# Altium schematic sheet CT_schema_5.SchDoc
size 176 x 147 mm
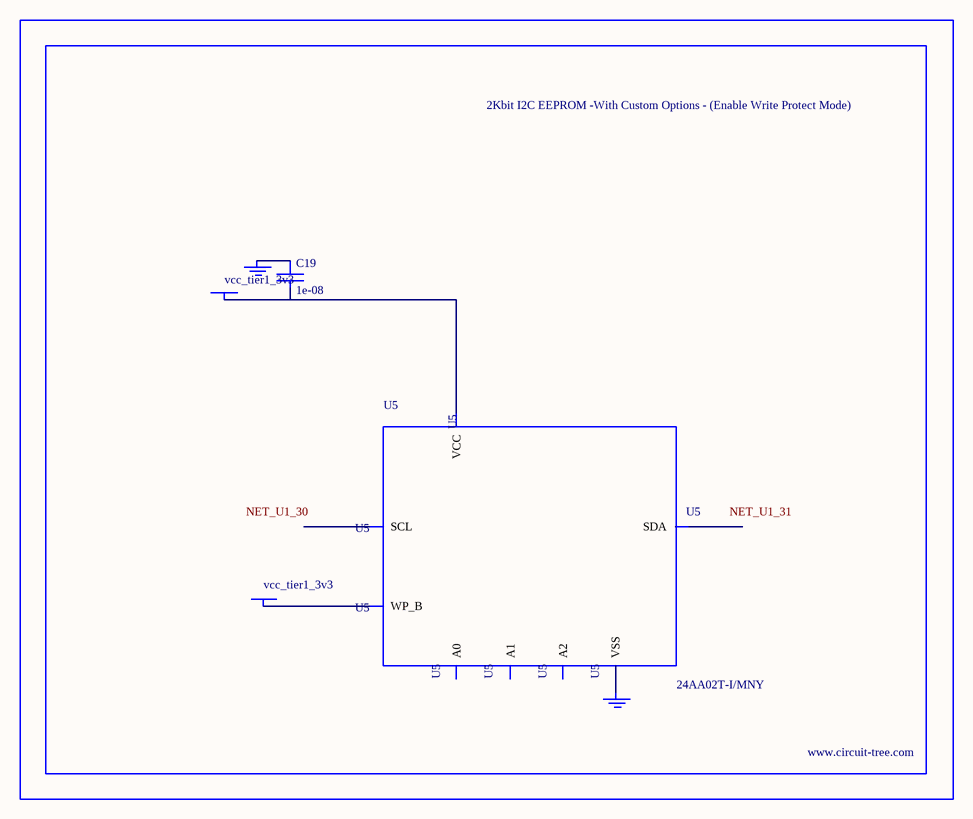
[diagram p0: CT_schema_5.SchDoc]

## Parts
BORDER4  (no value)
C19  1e-08  [C0402]
GND_INSTANCE_4_0  (no value)
GND_INSTANCE_4_1  (no value)
POWER_INSTANCE_4_0  vcc_tier1_3v3
POWER_INSTANCE_4_1  vcc_tier1_3v3
U5  24AA02T-I/MNY  [TDFN-8/6MM]

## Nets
NetC19_1: C19.1 GND_INSTANCE_4_0.0(GND)
NetC19_2: C19.2 POWER_INSTANCE_4_1.0(PWR) U5.8(VCC)
NetGND_INSTANCE_4_1_0: GND_INSTANCE_4_1.0(GND) U5.4(VSS)
NetPOWER_INSTANCE_4_0_0: POWER_INSTANCE_4_0.0(PWR) U5.7(WP_B)

Not connected (* = marked no-connect by the designer): U5 1(A0) 2(A1) 3(A2) 5(SDA) 6(SCL)

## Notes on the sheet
- Labels drawn without touching a wire or pin: NET_U1_30, NET_U1_31

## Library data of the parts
BORDER4 = BORDER_PAGE4
C19 = C0402C103K3RAC
GND_INSTANCE_4_0 GND_INSTANCE_4_1 = GND
POWER_INSTANCE_4_0 POWER_INSTANCE_4_1 = PWR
